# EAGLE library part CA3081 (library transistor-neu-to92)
TRANSISTOR ARRAY general purpose, high current common emitter
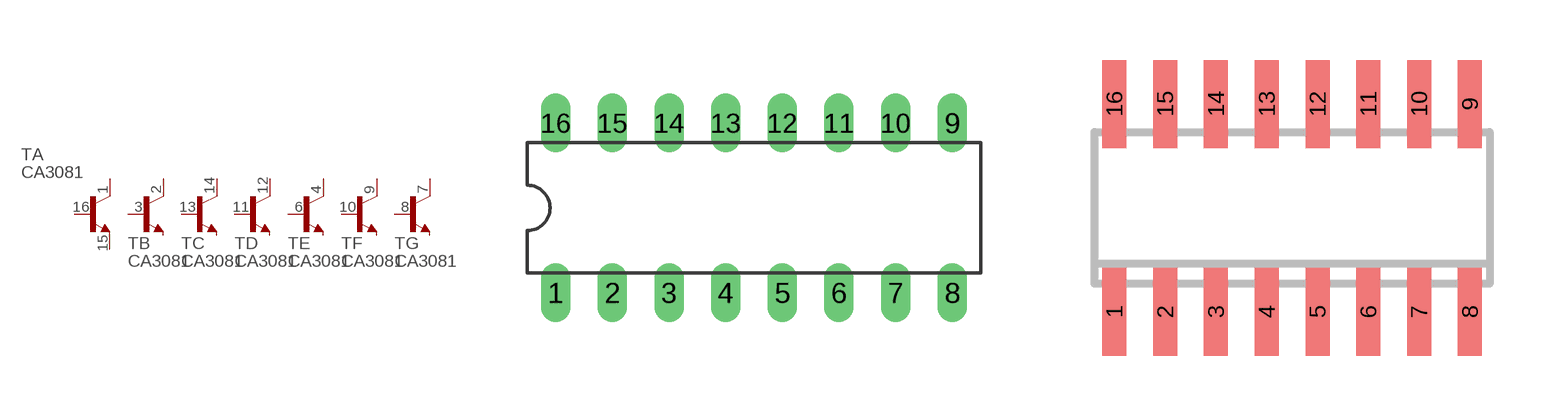
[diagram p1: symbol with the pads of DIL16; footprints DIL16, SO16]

Designator prefix T; gates A=NPN-PAD B=NPN-C C=NPN-C D=NPN-C E=NPN-C F=NPN-C G=NPN-C

## CA3081  [DIL16]
1  A:C  pas
2  B:C  pas
3  B:B  pas
4  E:C  pas
6  E:B  pas
7  G:C  pas
8  G:B  pas
9  F:C  pas
10  F:B  pas
11  D:B  pas
12  D:C  pas
13  C:B  pas
14  C:C  pas
15  A:E  pas
16  A:B  pas

## CA3081M  [SO16]
Pads as for DIL16

## Footprint DIL16 (pad centres in mm)
Dual In Line Package
drill 0.813 long: 1 -8.89,-3.81; 2 -6.35,-3.81; 3 -3.81,-3.81; 4 -1.27,-3.81; 5 1.27,-3.81; 6 3.81,-3.81; 7 6.35,-3.81; 8 8.89,-3.81; 9 8.89,3.81; 10 6.35,3.81; 11 3.81,3.81; 12 1.27,3.81; 13 -1.27,3.81; 14 -3.81,3.81; 15 -6.35,3.81; 16 -8.89,3.81

## Footprint SO16 (pad centres in mm)
SMALL OUTLINE INTEGRATED CIRCUIT body 3.9 mm/JEDEC MS-012AC
smd 0.6 x 2.2: 1 -4.445,-2.6; 2 -3.175,-2.6; 3 -1.905,-2.6; 4 -0.635,-2.6; 5 0.635,-2.6; 6 1.905,-2.6; 7 3.175,-2.6; 8 4.445,-2.6; 9 4.445,2.6; 10 3.175,2.6; 11 1.905,2.6; 12 0.635,2.6; 13 -0.635,2.6; 14 -1.905,2.6; 15 -3.175,2.6; 16 -4.445,2.6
